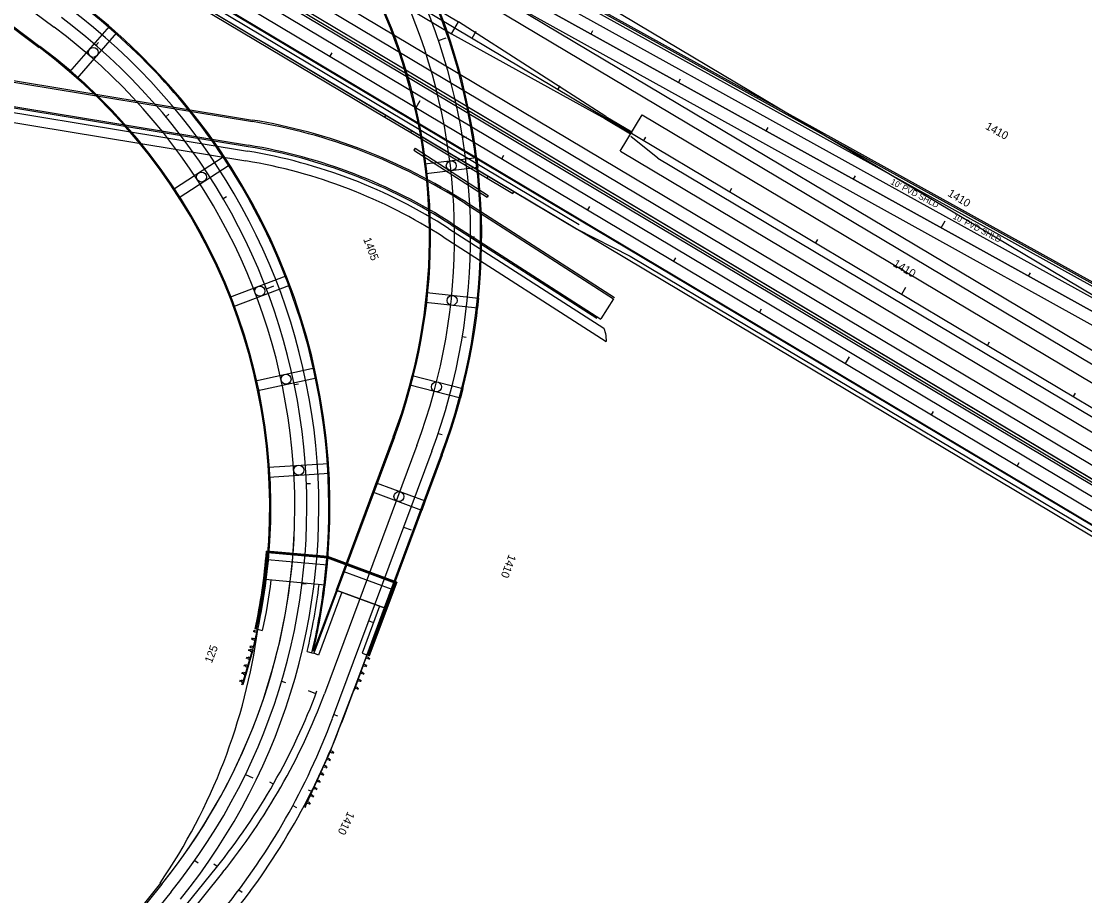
# Model space of a CAD drawing. Extents: x 2339272 to 2351734, y 366540 to 375057.
# Drawn here: x 2346509 to 2347572, y 368623 to 369498 of the extents above; entities that cross this region are included whole.
import ezdxf

# ---------------------------------------------------------------- set-up
doc = ezdxf.new("R2010")
doc.units = 0
for name, color, linetype in [('RD_HC_Cl', 7, 'Continuous'), ('RD_HC_CL_Rel', 7, 'Continuous'), ('RD_HC_Data_Tic', 7, 'Continuous'), ('RD_HC_Data_Tic_Rel', 7, 'Continuous'), ('RD_HC_TX_Rel_Sta50', 7, 'Continuous'), ('RD_HC_TX_Sta50', 7, 'Continuous'), ('RD_PD_Bridge', 7, 'Continuous'), ('RD_PD_CLEARZONE', 7, 'Continuous'), ('RD_PD_Final_LnLine', 7, 'Continuous'), ('RD_PD_Final_TrvlWay', 7, 'Continuous'), ('RD_PD_FOC', 7, 'Continuous'), ('RD_PD_GR', 7, 'Continuous'), ('RD_PD_MedBWall', 7, 'Continuous'), ('RD_PD_MedGR', 7, 'Continuous'), ('RD_PD_NOISE-WALL-GM', 7, 'Continuous'), ('RD_PD_PaveShd', 7, 'Continuous'), ('RD_PD_SW', 7, 'Continuous'), ('RD_PD_WallFill', 7, 'Continuous')]:
    doc.layers.add(name, color=color, linetype=linetype)

# ---------------------------------------------------------------- blocks, each defined once
blk = doc.blocks.new('Guardrail_MTBBC2_Transition')
at = {"layer": 'RD_PD_GR'}
for p, q in [((0, 0.5), (0, 0)), ((21.25, 0.5), (0, 0.5)), ((0, 0), (21.25, 0)), ((3.875, 3.75), (2.125, 3.75)), ((2.125, 0.5), (2.125, 2.5)), ((2.125, 2.5), (3.875, 2.5)), ((3.875, 0.5), (2.125, 0.5)), ((3, 2.5), (3, 3.75)), ((3.875, 2.5), (3.875, 0.5)), ((11.875, 3.75), (10.125, 3.75)), ((10.125, 0.5), (10.125, 2.5)), ((10.125, 2.5), (11.875, 2.5)), ((11.875, 0.5), (10.125, 0.5)), ((11, 2.5), (11, 3.75)), ((11.875, 2.5), (11.875, 0.5)), ((15, 0.5), (15, 0)), ((19.875, 3.75), (18.125, 3.75)), ((18.125, 0.5), (18.125, 2.5)), ((18.125, 2.5), (19.875, 2.5)), ((19.875, 0.5), (18.125, 0.5)), ((19, 2.5), (19, 3.75)), ((19.875, 2.5), (19.875, 0.5)), ((21.25, 0), (21.25, 0.5))]:
    blk.add_line(p, q, dxfattribs=at)
blk = doc.blocks.new('Guardrail_MB_Trailing_without_Buffer')
at = {"layer": 'RD_PD_GR'}
for p, q in [((1.75, 3.75), (0, 3.75)), ((0, 0.5), (0, 2.5)), ((0, 2.5), (1.75, 2.5)), ((1.75, 0.5), (0, 0.5)), ((35, 0.5), (0, 0.5)), ((0, 0.5), (0, 0)), ((0, 0), (36, 0)), ((0.875, 2.5), (0.875, 3.75)), ((1.75, 2.5), (1.75, 0.5)), ((9.75, 3.75), (8, 3.75)), ((8, 0.5), (8, 2.5)), ((8, 2.5), (9.75, 2.5)), ((9.75, 0.5), (8, 0.5)), ((8.875, 2.5), (8.875, 3.75)), ((9.75, 2.5), (9.75, 0.5)), ((17.75, 3.75), (16, 3.75)), ((16, 0.5), (16, 2.5)), ((16, 2.5), (17.75, 2.5)), ((17.75, 0.5), (16, 0.5)), ((16.875, 2.5), (16.875, 3.75)), ((17.75, 2.5), (17.75, 0.5)), ((25.75, 3.75), (24, 3.75)), ((24, 0.5), (24, 2.5)), ((24, 2.5), (25.75, 2.5)), ((25.75, 0.5), (24, 0.5)), ((24.875, 2.5), (24.875, 3.75)), ((25.75, 2.5), (25.75, 0.5)), ((33.75, 3.75), (32, 3.75)), ((32, 0.5), (32, 2.5)), ((32, 2.5), (33.75, 2.5)), ((33.75, 0.5), (32, 0.5)), ((32.875, 2.5), (32.875, 3.75)), ((33.75, 2.5), (33.75, 0.5)), ((36, 1), (35, 1)), ((35, 1), (35, 0.502)), ((36, 0), (36, 1))]:
    blk.add_line(p, q, dxfattribs=at)
blk = doc.blocks.new('Guardrail_MT3_Leading_without_Buffer')
at = {"layer": 'RD_PD_GR'}
for p, q in [((1.6, 3.8), (-0.1, 3.7)), ((-0.1, 2.5), (1.7, 2.6)), ((0, 0.5), (-0.1, 2.5)), ((61, 2.5), (0, 0.5)), ((0, 0), (62, 2)), ((1.7, 0.6), (0, 0.5)), ((0, 0.5), (0, 0)), ((0.8, 2.5), (0.8, 3.8)), ((1.7, 2.6), (1.7, 0.6)), ((9.6, 4.1), (7.9, 4)), ((8, 0.8), (7.9, 2.8)), ((7.9, 2.8), (9.7, 2.8)), ((9.7, 0.8), (8, 0.8)), ((8.8, 2.8), (8.7, 4)), ((9.7, 2.8), (9.7, 0.8)), ((17.6, 4.3), (15.9, 4.3)), ((15.9, 3), (17.7, 3.1)), ((16, 1), (15.9, 3)), ((17.7, 1.1), (16, 1)), ((16.8, 3), (16.7, 4.3)), ((17.7, 3.1), (17.7, 1.1)), ((25.6, 4.6), (23.9, 4.5)), ((24, 1.3), (23.9, 3.3)), ((23.9, 3.3), (25.7, 3.3)), ((25.7, 1.3), (24, 1.3)), ((24.8, 3.3), (24.7, 4.6)), ((25.7, 3.3), (25.7, 1.3)), ((33.6, 4.8), (31.9, 4.8)), ((31.9, 3.5), (33.7, 3.6)), ((32, 1.5), (31.9, 3.5)), ((33.7, 1.6), (32, 1.5)), ((32.8, 3.6), (32.7, 4.8)), ((33.7, 3.6), (33.7, 1.6)), ((41.6, 5.1), (39.9, 5)), ((40, 1.8), (39.9, 3.8)), ((39.9, 3.8), (41.6, 3.8)), ((41.7, 1.8), (40, 1.8)), ((40.8, 3.8), (40.7, 5.1)), ((41.6, 3.8), (41.7, 1.8)), ((45.1, -2.3), (45, 1.5)), ((49.6, 5.4), (47.9, 5.3)), ((47.9, 4), (49.6, 4.1)), ((48, 2), (47.9, 4)), ((49.7, 2.1), (48, 2)), ((48.8, 4.1), (48.7, 5.3)), ((49.6, 4.1), (49.7, 2.1)), ((57.6, 5.6), (55.8, 5.6)), ((55.9, 4.3), (57.6, 4.4)), ((56, 2.3), (55.9, 4.3)), ((57.7, 2.4), (56, 2.3)), ((56.8, 4.3), (56.7, 5.6)), ((57.6, 4.4), (57.7, 2.4)), ((61.9, 3), (60.9, 3)), ((60.9, 3), (61, 2.5)), ((62, 2), (61.9, 3))]:
    blk.add_line(p, q, dxfattribs=at)
blk = doc.blocks.new('Guardrail_MTBBC3_Transition')
at = {"layer": 'RD_PD_GR'}
for p, q in [((37, 0.5), (0, 0.5)), ((0, 0.5), (0, 0)), ((0, 0), (37, 0)), ((3.525, 3.75), (1.775, 3.75)), ((1.775, 0.5), (1.775, 2.5)), ((1.775, 2.5), (3.525, 2.5)), ((3.525, 0.5), (1.775, 0.5)), ((2.65, 2.5), (2.65, 3.75)), ((3.525, 2.5), (3.525, 0.5)), ((11.525, 3.75), (9.775, 3.75)), ((9.775, 0.5), (9.775, 2.5)), ((9.775, 2.5), (11.525, 2.5)), ((11.525, 0.5), (9.775, 0.5)), ((10.65, 2.5), (10.65, 3.75)), ((11.525, 2.5), (11.525, 0.5)), ((19.525, 3.75), (17.775, 3.75)), ((17.775, 0.5), (17.775, 2.5)), ((17.775, 2.5), (19.525, 2.5)), ((19.525, 0.5), (17.775, 0.5)), ((18.65, 2.5), (18.65, 3.75)), ((19.525, 2.5), (19.525, 0.5)), ((27.525, 3.75), (25.775, 3.75)), ((25.775, 0.5), (25.775, 2.5)), ((25.775, 2.5), (27.525, 2.5)), ((27.525, 0.5), (25.775, 0.5)), ((26.65, 2.5), (26.65, 3.75)), ((27.525, 2.5), (27.525, 0.5)), ((30.65, 0.5), (30.65, 0)), ((35.525, 3.75), (33.775, 3.75)), ((33.775, 0.5), (33.775, 2.5)), ((33.775, 2.5), (35.525, 2.5)), ((35.525, 0.5), (33.775, 0.5)), ((34.65, 2.5), (34.65, 3.75)), ((35.525, 2.5), (35.525, 0.5)), ((37, 0), (37, 0.5))]:
    blk.add_line(p, q, dxfattribs=at)

msp = doc.modelspace()

# ---------------------------------------------------------------- linework, layer by layer
at = {"layer": 'RD_HC_Cl'}
for p, q in [((2346281.6, 369885.4), (2351112.4, 367003.2)), ((2346606.5, 369804.5), (2348463.1, 368696.8)), ((2346606.5, 369804.5), (2348463.1, 368696.8)), ((2346606.5, 369804.5), (2348463.1, 368696.8)), ((2346606.5, 369804.5), (2348463.1, 368696.8)), ((2346919, 369067.9), (2346819.4, 368800.4)), ((2346059.3, 367853.2), (2346703.6, 368651.5)), ((2346658.3, 368627.2), (2346625.9, 368587.1))]:
    msp.add_line(p, q, dxfattribs=at)
for centre, radius, start, end in [((2346341.6, 369282.7), 616, 339.5935, 61.7249), ((2346182, 369011.6), 612, 321.0938, 53.1918), ((2346211.8, 369048.5), 632, 321.0938, 339.5935), ((2346178.4, 369038.9), 684, 321.0938, 339.5935)]:
    msp.add_arc(centre, radius, start, end, dxfattribs=at)
at = {"layer": 'RD_HC_CL_Rel'}
for p, q in [((2346236.3, 369809.5), (2347935.6, 368795.6)), ((2346990.8, 369533.5), (2347672.4, 369155.9))]:
    msp.add_line(p, q, dxfattribs=at)
at = {"layer": 'RD_HC_Data_Tic'}
for p, q in [((2346959.2, 369481.1), (2346963.3, 369488)), ((2346583.2, 369473.7), (2346585.8, 369476.7)), ((2346925.6, 369478.8), (2346933.2, 369481.3)), ((2347045.1, 369429.9), (2347047.1, 369433.3)), ((2346653, 369402.3), (2346656.1, 369404.8)), ((2346949.6, 369381.8), (2346953.6, 369382.4)), ((2347131, 369378.7), (2347133, 369382.1)), ((2347216.8, 369327.4), (2347218.9, 369330.9)), ((2346710.3, 369320.5), (2346713.8, 369322.5)), ((2346957.6, 369282.2), (2346961.6, 369282.2)), ((2347302.7, 369276.2), (2347304.8, 369279.6)), ((2346753.5, 369230.4), (2346761, 369233.3)), ((2347388.6, 369225), (2347392.7, 369231.8)), ((2346949.4, 369182.7), (2346953.4, 369182)), ((2347474.5, 369173.7), (2347476.5, 369177.2)), ((2346781.5, 369134.5), (2346785.5, 369135.3)), ((2347560.3, 369122.5), (2347562.4, 369125.9)), ((2346925.3, 369085.7), (2346929.1, 369084.5)), ((2346793.5, 369035.4), (2346797.5, 369035.5)), ((2346890.7, 368991.9), (2346898.2, 368989.1)), ((2346789.3, 368935.6), (2346793.2, 368935.1)), ((2346855.8, 368898.2), (2346859.6, 368896.8)), ((2346768.8, 368837.8), (2346772.7, 368836.6)), ((2346803.1, 368825.3), (2346795.6, 368828.1)), ((2346821, 368804.5), (2346824.7, 368803.1)), ((2346732.7, 368744.6), (2346739.9, 368741.2)), ((2346760.5, 368734.9), (2346757.1, 368736.9)), ((2346779.9, 368713.4), (2346783.5, 368711.5)), ((2346682, 368658.6), (2346685.3, 368656.3)), ((2346704.3, 368652.4), (2346701.1, 368654.9)), ((2346726.1, 368629.2), (2346729.3, 368626.8))]:
    msp.add_line(p, q, dxfattribs=at)
at = {"layer": 'RD_HC_Data_Tic_Rel'}
for p, q in [((2347078.1, 369485.2), (2347080, 369488.7)), ((2346817.2, 369462.9), (2346819.2, 369466.3)), ((2347165.6, 369436.7), (2347167.5, 369440.2)), ((2346903.1, 369411.7), (2346907.2, 369418.5)), ((2347253, 369388.2), (2347255, 369391.7)), ((2346988.9, 369360.4), (2346991, 369363.9)), ((2347340.5, 369339.8), (2347342.4, 369343.3)), ((2347074.8, 369309.2), (2347076.9, 369312.6)), ((2347428, 369291.3), (2347431.9, 369298.3)), ((2347160.7, 369258), (2347162.7, 369261.4)), ((2347515.4, 369242.9), (2347517.4, 369246.4)), ((2347246.6, 369206.7), (2347248.6, 369210.2)), ((2347332.4, 369155.5), (2347336.5, 369162.4)), ((2347418.3, 369104.3), (2347420.4, 369107.7)), ((2347504.2, 369053), (2347506.2, 369056.5))]:
    msp.add_line(p, q, dxfattribs=at)
at = {"layer": 'RD_PD_Bridge'}
for p, q in [((2346845.9, 369556.8), (2346945.7, 369497.2)), ((2346838.8, 369544.9), (2346938.6, 369485.4)), ((2346459.9, 369521.6), (2346526.4, 369471.8)), ((2346460.6, 369522.5), (2346527.1, 369472.7)), ((2346938.6, 369485.4), (2346945.7, 369497.2)), ((2346556.9, 369447.4), (2346596.6, 369492.8)), ((2346564.4, 369440.8), (2346604.1, 369486.2)), ((2346872.1, 369401.8), (2346873.3, 369403.8)), ((2346872.1, 369401.8), (2346897.8, 369386.5)), ((2346873.3, 369403.8), (2346899, 369388.5)), ((2346897.8, 369386.5), (2346899, 369388.5)), ((2346897.8, 369386.5), (2346999.9, 369325.6)), ((2346899, 369388.5), (2347001.1, 369327.6)), ((2346902.1, 369370.9), (2346900.8, 369368.9)), ((2346902.1, 369370.9), (2346975.4, 369323.7)), ((2346660.7, 369329.9), (2346711.2, 369362.8)), ((2346900.8, 369368.9), (2346974.2, 369321.8)), ((2346666.2, 369321.5), (2346716.7, 369354.4)), ((2346974.1, 369340.9), (2346975.3, 369342.9)), ((2346999.9, 369325.6), (2347001.1, 369327.6)), ((2346975.4, 369323.7), (2346974.2, 369321.8)), ((2346717.1, 369221.8), (2346773.4, 369243.3)), ((2346720.7, 369212.5), (2346776.9, 369234)), ((2346742.8, 369138.4), (2346801.6, 369151.1)), ((2346744.9, 369128.6), (2346803.8, 369141.4)), ((2346880.4, 369082.3), (2346823.4, 368928.9)), ((2346881.5, 369081.9), (2346824.4, 368928.5)), ((2346928.3, 369064.4), (2346871.3, 368911.1)), ((2346929.4, 369064), (2346872.4, 368910.7)), ((2346755.5, 369052), (2346815.6, 369055.7)), ((2346756.1, 369042), (2346816.3, 369045.8)), ((2346814.5, 368953.8), (2346754.5, 368959.3)), ((2346879.3, 368929.5), (2346830.4, 368947.7)), ((2346812.3, 368934), (2346752.4, 368939.4)), ((2346872.4, 368910.7), (2346823.4, 368928.9))]:
    msp.add_line(p, q, dxfattribs=at)
for points in [[(2346963.8, 369361.5), (2346965, 369351.5), (2346913.1, 369345.4), (2346911.9, 369355.3)], [(2346965.7, 369220.9), (2346964.6, 369211), (2346912.7, 369216.5), (2346913.8, 369226.5)], [(2346950, 369130.5), (2346947.5, 369120.8), (2346896.9, 369133.9), (2346899.4, 369143.6)], [(2346912.3, 369018.1), (2346908.8, 369008.7), (2346859.8, 369026.9), (2346863.3, 369036.3)]]:
    msp.add_lwpolyline(points, close=True, dxfattribs=at)
for centre in [(2346580.5, 369466.8), (2346938.4, 369353.4), (2346688.7, 369342.1), (2346747, 369227.9), (2346939.2, 369218.7), (2346773.2, 369139.9), (2346923.5, 369132.2), (2346785.9, 369048.9), (2346886.1, 369022.5)]:
    msp.add_circle(centre, 5, dxfattribs=at)
for centre, radius, start, end in [((2346341.6, 369282.7), 626, 339.5935, 61.7249), ((2346341.6, 369282.7), 627.1, 339.5935, 61.7249), ((2346341.6, 369282.7), 574.9, 339.5935, 58.038), ((2346341.6, 369282.7), 576, 339.5935, 58.038), ((2346182, 369011.6), 635.1, 352.9805, 53.1918), ((2346182, 369011.6), 634, 31.6599, 51.3834), ((2346182, 369011.6), 574.9, 352.7914, 53.1918), ((2346182, 369011.6), 576, 352.7952, 53.1918), ((2346182, 369011.6), 634, 352.9773, 31.6599)]:
    msp.add_arc(centre, radius, start, end, dxfattribs=at)
at = {"layer": 'RD_PD_Final_LnLine'}
for p, q in [((2346262.5, 369853.5), (2348279.8, 368650)), ((2346236.3, 369809.5), (2347935.6, 368795.6)), ((2346236.7, 369794.6), (2347945.2, 368775.3)), ((2346236.7, 369794.6), (2347945.2, 368775.3)), ((2346236.7, 369794.6), (2347945.2, 368775.3)), ((2346236.7, 369794.6), (2347945.2, 368775.3)), ((2347672.4, 369155.9), (2346990.8, 369533.5)), ((2346978.7, 369512.8), (2348317.9, 368713.8)), ((2346482.4, 369440.1), (2346739.5, 369397.6)), ((2346482.4, 369440.1), (2346739.5, 369397.6)), ((2346478.5, 369416.4), (2346735.6, 369374)), ((2346951.9, 369315.9), (2347100.6, 369220.4)), ((2346939, 369295.7), (2347087.9, 369200)), ((2347100.6, 369220.4), (2347087.7, 369200.3)), ((2346919, 369067.9), (2346819.4, 368800.4)), ((2346648.9, 368634.7), (2346565.4, 368531.3))]:
    msp.add_line(p, q, dxfattribs=at)
for centre, radius, start, end in [((2346341.6, 369282.7), 616, 339.5935, 61.7249), ((2346182, 369011.6), 612, 321.0938, 53.1918), ((2346182, 369011.6), 600, 321.0938, 53.1918), ((2346648.1, 368843.1), 562, 57.2694, 80.6339), ((2346648.1, 368843.1), 562, 57.2694, 80.6339), ((2346648.1, 368843.1), 538, 57.2694, 80.6339), ((2346182, 369011.6), 600, 321.0938, 357.5005)]:
    msp.add_arc(centre, radius, start, end, dxfattribs=at)
at = {"layer": 'RD_PD_Final_TrvlWay'}
for p, q in [((2345710.1, 370114.1), (2346541.5, 369491.9)), ((2346256.4, 369843.2), (2348273.5, 368639.7)), ((2346242.4, 369819.8), (2347941.8, 368805.9)), ((2346217.6, 369806.6), (2347929.5, 368785.3)), ((2346996.8, 369543.9), (2347678.2, 369166.4)), ((2346984.8, 369523.1), (2348324.1, 368724.1)), ((2347390, 369298.6), (2346984.8, 369523.1)), ((2347666.5, 369145.4), (2347390, 369298.6)), ((2346904, 369073.5), (2346811.6, 368825.3)), ((2346823.4, 368928.9), (2346872.4, 368910.7)), ((2346709.8, 368646.5), (2346511.9, 368401.3))]:
    msp.add_line(p, q, dxfattribs=at)
for centre, radius, start, end in [((2346341.6, 369282.7), 600, 339.5935, 61.7249), ((2346182, 369011.6), 624, 321.0938, 53.1918), ((2346211.8, 369048.5), 640, 321.0938, 339.5935)]:
    msp.add_arc(centre, radius, start, end, dxfattribs=at)
at = {"layer": 'RD_PD_FOC'}
for p, q in [((2346482.6, 369441.5), (2346739.8, 369399.1)), ((2346478.2, 369414.9), (2346735.4, 369372.5)), ((2346952.8, 369317.2), (2347101.4, 369221.6)), ((2346938.2, 369294.4), (2347083.9, 369200.8)), ((2346647.8, 368635.7), (2346564.3, 368532.2))]:
    msp.add_line(p, q, dxfattribs=at)
for radius in [563.5, 536.5]:
    msp.add_arc((2346648.1, 368843.1), radius, 57.2694, 80.6339, dxfattribs=at)
at = {"layer": 'RD_PD_GR'}
for p, q in [((2347001.1, 369327.6), (2347924.4, 368776.7)), ((2346841, 368829.6), (2346817.6, 368768.6))]:
    msp.add_line(p, q, dxfattribs=at)
at = {"layer": 'RD_PD_MedBWall'}
for p, q in [((2346321.7, 369738.8), (2347066.1, 369294.6)), ((2346337.8, 369720.6), (2346872.1, 369401.8)), ((2346339.2, 369722.5), (2346873.3, 369403.8)), ((2347683, 369175.2), (2347001.8, 369552.6)), ((2347684.2, 369177.2), (2347002.9, 369554.6)), ((2346753.4, 369526.6), (2347946.9, 368814.5)), ((2346754.6, 369528.6), (2347948.1, 368816.5)), ((2347093, 369402.6), (2346945.7, 369497.2)), ((2346938.6, 369485.4), (2347091.8, 369400.6)), ((2347093, 369402.7), (2347118.8, 369387.3)), ((2347091.8, 369400.6), (2347117.6, 369385.3)), ((2347118.8, 369387.3), (2347117.6, 369385.3)), ((2346823.5, 368928.9), (2346800.8, 368867.9)), ((2346824.4, 368928.5), (2346801.1, 368865.7)), ((2346829.1, 368926.8), (2346805.7, 368863.9)), ((2346866.6, 368912.9), (2346849.2, 368866)), ((2346871.3, 368911.1), (2346853.9, 368864.2)), ((2346871.3, 368911.1), (2346853.9, 368864.2)), ((2346872.4, 368910.7), (2346855, 368863.8)), ((2346743.7, 368889.7), (2346744.9, 368889.4)), ((2346749.8, 368888.3), (2346744.9, 368889.4)), ((2346794.3, 368867.4), (2346799.1, 368866.3)), ((2346799.1, 368866.3), (2346801.1, 368865.7)), ((2346800.6, 368867.9), (2346800.8, 368867.9)), ((2346805.7, 368863.9), (2346801.1, 368865.7)), ((2346849.2, 368866), (2346853.9, 368864.2)), ((2346855, 368863.8), (2346853.9, 368864.2))]:
    msp.add_line(p, q, dxfattribs=at)
for radius, start, end in [(574.8, 347.7564, 352.7911), (576, 347.7564, 352.7911), (581, 347.7564, 352.8124), (629, 346.7521, 352.9773), (634, 346.7521, 352.9773), (635, 346.9273, 352.9802)]:
    msp.add_arc((2346182, 369011.6), radius, start, end, dxfattribs=at)
at = {"layer": 'RD_PD_MedGR'}
for q in [(2347117.8, 369382.6), (2349123.2, 368180.7)]:
    msp.add_line((2347144.9, 369361), q, dxfattribs=at)
at = {"layer": 'RD_PD_NOISE-WALL-GM'}
for p, q in [((2347684.2, 369177.2), (2347002.9, 369554.6)), ((2347684.9, 369178.5), (2347003.7, 369555.9))]:
    msp.add_line(p, q, dxfattribs=at)
at = {"layer": 'RD_PD_PaveShd'}
for p, q in [((2346247.5, 369828.4), (2347946.9, 368814.5)), ((2346250.2, 369832.9), (2347949.6, 368819)), ((2346250.2, 369832.9), (2348267.5, 368629.3)), ((2346319.1, 369734.5), (2347063.5, 369290.3)), ((2347683, 369175.2), (2347001.8, 369552.6)), ((2347107.3, 369368.1), (2347129.1, 369404.4)), ((2347129.1, 369404.4), (2348309.7, 368700)), ((2347107.4, 369368.1), (2348288, 368663.7)), ((2347063.5, 369290.3), (2347117.1, 369263)), ((2347117.1, 369263), (2347926.4, 368780.2)), ((2346928.3, 369064.4), (2346828.8, 368796.9)), ((2346824.4, 368928.5), (2346821.1, 368919.6))]:
    msp.add_line(p, q, dxfattribs=at)
for centre, radius, start, end in [((2346161.4, 368968.5), 588.8, 325.6153, 352.2779), ((2346178.4, 369038.9), 694, 321.0938, 339.5935)]:
    msp.add_arc(centre, radius, start, end, dxfattribs=at)
at = {"layer": 'RD_PD_SW'}
for p, q in [((2346477.5, 369410.5), (2346734.7, 369368)), ((2346475.9, 369400.6), (2346733, 369358.2)), ((2346935.7, 369290.7), (2347091, 369190.9)), ((2346930.3, 369282.2), (2347093.2, 369177.5)), ((2347091, 369190.9), (2347092.6, 369185.7)), ((2347092.6, 369185.7), (2347093, 369183.1)), ((2347093, 369183.1), (2347093.2, 369177.6)), ((2347093.2, 369177.6), (2347093.2, 369177.5))]:
    msp.add_line(p, q, dxfattribs=at)
for radius in [532, 522]:
    msp.add_arc((2346648.1, 368843.1), radius, 57.2694, 80.6339, dxfattribs=at)
at = {"layer": 'RD_PD_WallFill'}
for p, q in [((2346815.1, 368962.4), (2346753.6, 368967.8)), ((2346815, 368961.9), (2346754.1, 368967.3)), ((2346815, 368961.4), (2346754.6, 368966.7)), ((2346814.8, 368960.9), (2346755, 368966.2)), ((2346881.8, 368935.9), (2346814.8, 368960.9)), ((2346882.5, 368936.2), (2346814.9, 368961.4)), ((2346883.8, 368936.8), (2346815.1, 368962.4)), ((2346883.1, 368936.5), (2346815.1, 368961.8)), ((2346881.8, 368935.9), (2346855, 368863.8)), ((2346882.5, 368936.2), (2346855.5, 368863.7)), ((2346883.1, 368936.5), (2346855.9, 368863.5)), ((2346883.8, 368936.8), (2346856.4, 368863.3)), ((2346855, 368863.8), (2346856.4, 368863.3))]:
    msp.add_line(p, q, dxfattribs=at)
for radius, end in [(573.3, 355.6259), (573.8, 355.5753), (574.3, 355.5249)]:
    msp.add_arc((2346182, 369011.6), radius, 347.7564, end, dxfattribs=at)

# ---------------------------------------------------------------- block references
at = {"layer": 'RD_PD_CLEARZONE', "rotation": 76.70257401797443}
msp.add_blockref('Guardrail_MTBBC2_Transition', (2346740, 368868.7), dxfattribs=at)
at = {"layer": 'RD_PD_PaveShd', "yscale": -1.0000000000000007, "rotation": -106.13130991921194}
msp.add_blockref('Guardrail_MB_Trailing_without_Buffer', (2346740, 368868.8), dxfattribs=at)
at = {"layer": 'RD_PD_PaveShd'}
for name, p, rotation in [('Guardrail_MTBBC3_Transition', (2346853.9, 368864.2), -110.40598638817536), ('Guardrail_MT3_Leading_without_Buffer', (2346817.6, 368768.6), -116.63689620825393)]:
    msp.add_blockref(name, p, dxfattribs=dict(at, rotation=rotation))

# ---------------------------------------------------------------- texts
at = {"layer": 'RD_HC_TX_Rel_Sta50'}
for rotation, p in [(331.0137, (2347471.6, 369390.6)), (329.1785, (2347379.2, 369253.4))]:
    msp.add_text('1410', height=8, rotation=rotation, dxfattribs=at).set_placement(p)
at = {"layer": 'RD_HC_TX_Sta50'}
for s, rotation, p in [('1410', 329.1785, (2347433.9, 369323.7)), ('1405', 290.9528, (2346850.2, 369279.9)), ('1410', 249.5935, (2346996, 368965.2)), ('125', 69.3199, (2346699, 368855.3)), ('1410', 244.1425, (2346835, 368708))]:
    msp.add_text(s, height=8, rotation=rotation, dxfattribs=at).set_placement(p)
at = {"layer": 'RD_PD_Final_LnLine'}
for p in [(2347376.9, 369335.4), (2347439.3, 369300.8)]:
    msp.add_text("10' PVD SHLD", height=6, rotation=332.4, dxfattribs=at).set_placement(p)

doc.saveas('drawing.dxf')
